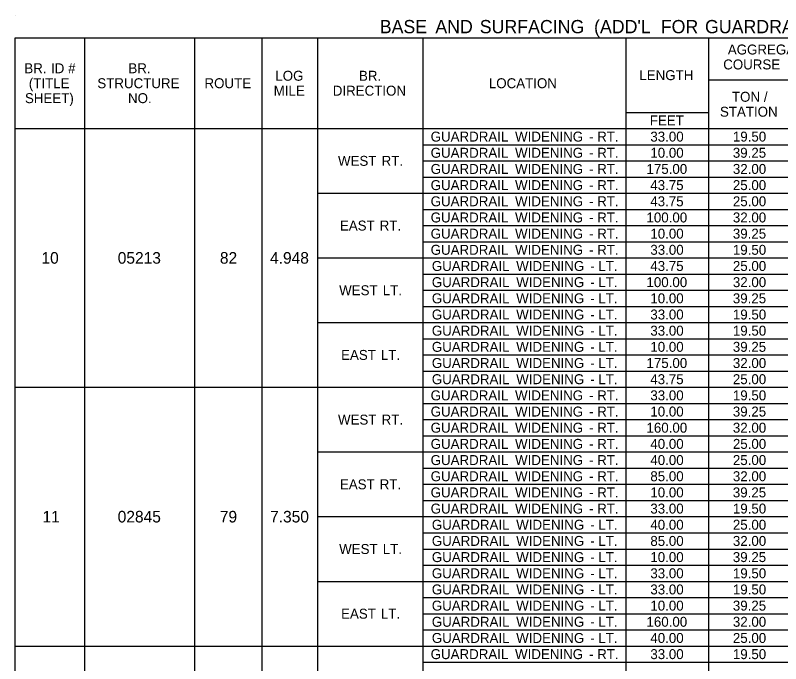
# Model space of a CAD drawing. Extents: x 544478 to 1930787, y -1948294 to 596640.
# Drawn here: x 554061.9 to 554523.1, y -1946526.7 to -1946135.8 of the extents above; entities that cross this region are included whole.
import ezdxf

# ---------------------------------------------------------------- set-up
doc = ezdxf.new("R2010")
doc.units = 0
doc.layers.add('Default', color=7, linetype='Continuous')

msp = doc.modelspace()

# ---------------------------------------------------------------- linework, layer by layer
at = {"layer": 'Default'}
for p, q in [((554061.9, -1946135.77), (554061.9, -1946135.77)), ((554061.9, -1946149.42), (554884.32, -1946149.42)), ((554061.9, -1946672.02), (554061.9, -1946149.42)), ((554103.83, -1946204.02), (554103.83, -1946149.42)), ((554170.13, -1946204.02), (554170.13, -1946149.42)), ((554210.59, -1946204.02), (554210.59, -1946149.42)), ((554244.23, -1946672.02), (554244.23, -1946149.42)), ((554307.6, -1946681.77), (554307.6, -1946149.42)), ((554429.97, -1946672.02), (554429.97, -1946149.42)), ((554479.69, -1946672.02), (554479.69, -1946149.42)), ((554479.69, -1946174.77), (554884.32, -1946174.77)), ((554429.97, -1946194.27), (554479.69, -1946194.27)), ((554479.69, -1946672.02), (554479.69, -1946194.27)), ((554061.9, -1946204.02), (554884.32, -1946204.02)), ((554103.83, -1946672.02), (554103.83, -1946204.02)), ((554170.13, -1946672.02), (554170.13, -1946204.02)), ((554210.59, -1946672.02), (554210.59, -1946204.02)), ((554429.97, -1946672.02), (554429.97, -1946204.02)), ((554479.69, -1946204.02), (554638.62, -1946204.02)), ((554307.6, -1946213.77), (554884.32, -1946213.77)), ((554307.6, -1946223.52), (554884.32, -1946223.52)), ((554307.6, -1946233.27), (554884.32, -1946233.27)), ((554244.23, -1946243.02), (554307.6, -1946243.02)), ((554307.6, -1946243.02), (554884.32, -1946243.02)), ((554307.6, -1946252.77), (554884.32, -1946252.77)), ((554307.6, -1946262.52), (554884.32, -1946262.52)), ((554307.6, -1946272.27), (554884.32, -1946272.27)), ((554244.23, -1946282.02), (554307.6, -1946282.02)), ((554307.6, -1946282.02), (554884.32, -1946282.02)), ((554307.6, -1946291.77), (554884.32, -1946291.77)), ((554307.6, -1946301.52), (554884.32, -1946301.52)), ((554307.6, -1946311.27), (554884.32, -1946311.27)), ((554244.23, -1946321.02), (554307.6, -1946321.02)), ((554307.6, -1946321.02), (554581.58, -1946321.02)), ((554307.6, -1946330.77), (554884.32, -1946330.77)), ((554307.6, -1946340.52), (554581.58, -1946340.52)), ((554307.6, -1946350.27), (554581.58, -1946350.27)), ((554061.9, -1946360.02), (554884.32, -1946360.02)), ((554307.6, -1946369.77), (554884.32, -1946369.77)), ((554307.6, -1946379.52), (554884.32, -1946379.52)), ((554307.6, -1946389.27), (554884.32, -1946389.27)), ((554244.23, -1946399.02), (554307.6, -1946399.02)), ((554307.6, -1946399.02), (554884.32, -1946399.02)), ((554307.6, -1946408.77), (554884.32, -1946408.77)), ((554307.6, -1946418.52), (554884.32, -1946418.52)), ((554307.6, -1946428.27), (554884.32, -1946428.27)), ((554244.23, -1946438.02), (554307.6, -1946438.02)), ((554307.6, -1946438.02), (554884.32, -1946438.02)), ((554307.6, -1946447.77), (554884.32, -1946447.77)), ((554307.6, -1946457.52), (554884.32, -1946457.52)), ((554307.6, -1946467.27), (554884.32, -1946467.27)), ((554244.23, -1946477.02), (554307.6, -1946477.02)), ((554307.6, -1946477.02), (554581.58, -1946477.02)), ((554307.6, -1946486.77), (554884.32, -1946486.77)), ((554307.6, -1946496.52), (554581.58, -1946496.52)), ((554307.6, -1946506.27), (554581.58, -1946506.27)), ((554061.9, -1946516.02), (554884.32, -1946516.02)), ((554307.6, -1946525.77), (554884.32, -1946525.77))]:
    msp.add_line(p, q, dxfattribs=at)

# ---------------------------------------------------------------- texts
for s, height, p in [('BASE', 8, (554281.5, -1946146.6)), (' AND', 8, (554312.01, -1946146.6)), (' SURFACING', 8, (554338.78, -1946146.6)), (" (ADD'L", 8, (554407.65, -1946146.6)), (' FOR', 8, (554447.85, -1946146.6)), (' GUARDRAIL)', 8, (554474.5, -1946146.6)), ('AGGREGATE', 6, (554491.22, -1946159.4)), ('BR.', 6, (554067.34, -1946170.72)), (' ID', 6, (554081.2, -1946170.72)), (' #', 6, (554091.5, -1946170.72)), ('BR.', 6, (554130.05, -1946170.72)), ('COURSE', 6, (554488.45, -1946168.4)), ('LOG', 6, (554218.58, -1946175.22)), ('BR.', 6, (554268.98, -1946175.22)), ('LENGTH', 6, (554437.92, -1946174.85)), ('(TITLE', 6, (554070.03, -1946179.72)), ('STRUCTURE', 6, (554111.33, -1946179.72)), ('ROUTE', 6, (554175.89, -1946179.72)), ('LOCATION', 6, (554347.23, -1946179.72)), ('MILE', 6, (554217.6, -1946184.22)), ('DIRECTION', 6, (554253.2, -1946184.22)), ('SHEET)', 6, (554067.71, -1946188.72)), ('NO.', 6, (554129.81, -1946188.72)), ('TON', 6, (554493.71, -1946187.9)), (' /', 6, (554510.73, -1946187.9)), ('STATION', 6, (554486.49, -1946196.9)), ('FEET', 6, (554444.2, -1946202.15)), ('GUARDRAIL', 6, (554312.17, -1946211.9)), (' WIDENING', 6, (554360.79, -1946211.9)), (' RT.', 6, (554410.29, -1946211.9)), ('33.00', 6, (554444.54, -1946211.9)), ('19.50', 6, (554494.27, -1946211.9)), (' -', 6, (554405.44, -1946211.9)), ('GUARDRAIL', 6, (554312.17, -1946221.65)), (' WIDENING', 6, (554360.79, -1946221.65)), (' RT.', 6, (554410.29, -1946221.65)), ('10.00', 6, (554444.54, -1946221.65)), ('39.25', 6, (554494.24, -1946221.65)), ('WEST', 6, (554256.34, -1946226.52)), (' -', 6, (554405.44, -1946221.65)), (' RT.', 6, (554280.39, -1946226.52)), ('GUARDRAIL', 6, (554312.17, -1946231.4)), (' WIDENING', 6, (554360.79, -1946231.4)), (' -', 6, (554405.44, -1946231.4)), (' RT.', 6, (554410.29, -1946231.4)), ('175.00', 6, (554442.21, -1946231.4)), ('32.00', 6, (554494.27, -1946231.4)), ('GUARDRAIL', 6, (554312.17, -1946241.15)), (' WIDENING', 6, (554360.79, -1946241.15)), (' -', 6, (554405.44, -1946241.15)), (' RT.', 6, (554410.29, -1946241.15)), ('43.75', 6, (554444.51, -1946241.15)), ('25.00', 6, (554494.27, -1946241.15)), ('GUARDRAIL', 6, (554312.17, -1946250.9)), (' WIDENING', 6, (554360.79, -1946250.9)), (' RT.', 6, (554410.29, -1946250.9)), ('43.75', 6, (554444.51, -1946250.9)), ('25.00', 6, (554494.27, -1946250.9)), (' -', 6, (554405.44, -1946250.9)), ('GUARDRAIL', 6, (554312.17, -1946260.65)), (' WIDENING', 6, (554360.79, -1946260.65)), (' RT.', 6, (554410.29, -1946260.65)), ('100.00', 6, (554442.21, -1946260.65)), ('32.00', 6, (554494.27, -1946260.65)), ('EAST', 6, (554257.5, -1946265.52)), (' RT.', 6, (554279.23, -1946265.52)), (' -', 6, (554405.44, -1946260.65)), ('GUARDRAIL', 6, (554312.17, -1946270.4)), (' WIDENING', 6, (554360.79, -1946270.4)), (' RT.', 6, (554410.29, -1946270.4)), ('10.00', 6, (554444.54, -1946270.4)), ('39.25', 6, (554494.24, -1946270.4)), (' -', 6, (554405.44, -1946270.4)), ('GUARDRAIL', 6, (554312.17, -1946280.15)), (' WIDENING', 6, (554360.79, -1946280.15)), (' RT.', 6, (554410.29, -1946280.15)), ('33.00', 6, (554444.54, -1946280.15)), ('19.50', 6, (554494.27, -1946280.15)), ('10', 7, (554077.66, -1946285.52)), ('05213', 7, (554123.61, -1946285.52)), ('82', 7, (554185.18, -1946285.52)), ('4.948', 7, (554215.39, -1946285.52)), (' -', 6, (554405.44, -1946280.15)), ('GUARDRAIL', 6, (554312.87, -1946289.9)), (' WIDENING', 6, (554361.49, -1946289.9)), (' LT.', 6, (554410.99, -1946289.9)), ('43.75', 6, (554444.51, -1946289.9)), ('25.00', 6, (554494.27, -1946289.9)), (' -', 6, (554406.14, -1946289.9)), ('GUARDRAIL', 6, (554312.87, -1946299.65)), (' WIDENING', 6, (554361.49, -1946299.65)), (' LT.', 6, (554410.99, -1946299.65)), ('100.00', 6, (554442.21, -1946299.65)), ('32.00', 6, (554494.27, -1946299.65)), ('WEST', 6, (554257.04, -1946304.52)), (' LT.', 6, (554281.09, -1946304.52)), (' -', 6, (554406.14, -1946299.65)), ('GUARDRAIL', 6, (554312.87, -1946309.4)), (' WIDENING', 6, (554361.49, -1946309.4)), (' LT.', 6, (554410.99, -1946309.4)), ('10.00', 6, (554444.54, -1946309.4)), ('39.25', 6, (554494.24, -1946309.4)), (' -', 6, (554406.14, -1946309.4)), ('GUARDRAIL', 6, (554312.87, -1946319.15)), (' WIDENING', 6, (554361.49, -1946319.15)), (' -', 6, (554406.14, -1946319.15)), (' LT.', 6, (554410.99, -1946319.15)), ('33.00', 6, (554444.54, -1946319.15)), ('19.50', 6, (554494.27, -1946319.15)), ('GUARDRAIL', 6, (554312.87, -1946328.9)), (' WIDENING', 6, (554361.49, -1946328.9)), (' -', 6, (554406.14, -1946328.9)), (' LT.', 6, (554410.99, -1946328.9)), ('33.00', 6, (554444.54, -1946328.9)), ('19.50', 6, (554494.27, -1946328.9)), ('GUARDRAIL', 6, (554312.87, -1946338.65)), (' WIDENING', 6, (554361.49, -1946338.65)), (' LT.', 6, (554410.99, -1946338.65)), ('10.00', 6, (554444.54, -1946338.65)), ('39.25', 6, (554494.24, -1946338.65)), ('EAST', 6, (554258.2, -1946343.52)), (' LT.', 6, (554279.93, -1946343.52)), (' -', 6, (554406.14, -1946338.65)), ('GUARDRAIL', 6, (554312.87, -1946348.4)), (' WIDENING', 6, (554361.49, -1946348.4)), (' LT.', 6, (554410.99, -1946348.4)), ('175.00', 6, (554442.21, -1946348.4)), ('32.00', 6, (554494.27, -1946348.4)), (' -', 6, (554406.14, -1946348.4)), ('GUARDRAIL', 6, (554312.87, -1946358.15)), (' WIDENING', 6, (554361.49, -1946358.15)), (' LT.', 6, (554410.99, -1946358.15)), ('43.75', 6, (554444.51, -1946358.15)), ('25.00', 6, (554494.27, -1946358.15)), (' -', 6, (554406.14, -1946358.15)), ('GUARDRAIL', 6, (554312.17, -1946367.9)), (' WIDENING', 6, (554360.79, -1946367.9)), (' RT.', 6, (554410.29, -1946367.9)), ('33.00', 6, (554444.54, -1946367.9)), ('19.50', 6, (554494.27, -1946367.9)), (' -', 6, (554405.44, -1946367.9)), ('GUARDRAIL', 6, (554312.17, -1946377.65)), (' WIDENING', 6, (554360.79, -1946377.65)), (' RT.', 6, (554410.29, -1946377.65)), ('10.00', 6, (554444.54, -1946377.65)), ('39.25', 6, (554494.24, -1946377.65)), ('WEST', 6, (554256.34, -1946382.52)), (' RT.', 6, (554280.39, -1946382.52)), (' -', 6, (554405.44, -1946377.65)), ('GUARDRAIL', 6, (554312.17, -1946387.4)), (' WIDENING', 6, (554360.79, -1946387.4)), (' RT.', 6, (554410.29, -1946387.4)), ('160.00', 6, (554442.21, -1946387.4)), ('32.00', 6, (554494.27, -1946387.4)), (' -', 6, (554405.44, -1946387.4)), ('GUARDRAIL', 6, (554312.17, -1946397.15)), (' WIDENING', 6, (554360.79, -1946397.15)), ('40.00', 6, (554444.54, -1946397.15)), ('25.00', 6, (554494.27, -1946397.15)), (' -', 6, (554405.44, -1946397.15)), (' RT.', 6, (554410.29, -1946397.15)), ('GUARDRAIL', 6, (554312.17, -1946406.9)), (' WIDENING', 6, (554360.79, -1946406.9)), (' -', 6, (554405.44, -1946406.9)), (' RT.', 6, (554410.29, -1946406.9)), ('40.00', 6, (554444.54, -1946406.9)), ('25.00', 6, (554494.27, -1946406.9)), ('GUARDRAIL', 6, (554312.17, -1946416.65)), (' WIDENING', 6, (554360.79, -1946416.65)), (' -', 6, (554405.44, -1946416.65)), (' RT.', 6, (554410.29, -1946416.65)), ('85.00', 6, (554444.54, -1946416.65)), ('32.00', 6, (554494.27, -1946416.65)), ('EAST', 6, (554257.5, -1946421.52)), (' RT.', 6, (554279.23, -1946421.52)), ('GUARDRAIL', 6, (554312.17, -1946426.4)), (' WIDENING', 6, (554360.79, -1946426.4)), (' RT.', 6, (554410.29, -1946426.4)), ('10.00', 6, (554444.54, -1946426.4)), ('39.25', 6, (554494.24, -1946426.4)), (' -', 6, (554405.44, -1946426.4)), ('GUARDRAIL', 6, (554312.17, -1946436.15)), (' WIDENING', 6, (554360.79, -1946436.15)), (' RT.', 6, (554410.29, -1946436.15)), ('33.00', 6, (554444.54, -1946436.15)), ('19.50', 6, (554494.27, -1946436.15)), ('11', 7, (554078.33, -1946441.52)), ('02845', 7, (554123.58, -1946441.52)), ('79', 7, (554185.14, -1946441.52)), ('7.350', 7, (554215.41, -1946441.52)), (' -', 6, (554405.44, -1946436.15)), ('GUARDRAIL', 6, (554312.87, -1946445.9)), (' WIDENING', 6, (554361.49, -1946445.9)), (' LT.', 6, (554410.99, -1946445.9)), ('40.00', 6, (554444.54, -1946445.9)), ('25.00', 6, (554494.27, -1946445.9)), (' -', 6, (554406.14, -1946445.9)), ('GUARDRAIL', 6, (554312.87, -1946455.65)), (' WIDENING', 6, (554361.49, -1946455.65)), (' LT.', 6, (554410.99, -1946455.65)), ('85.00', 6, (554444.54, -1946455.65)), ('32.00', 6, (554494.27, -1946455.65)), ('WEST', 6, (554257.04, -1946460.52)), (' LT.', 6, (554281.09, -1946460.52)), (' -', 6, (554406.14, -1946455.65)), ('GUARDRAIL', 6, (554312.87, -1946465.4)), (' WIDENING', 6, (554361.49, -1946465.4)), (' LT.', 6, (554410.99, -1946465.4)), ('10.00', 6, (554444.54, -1946465.4)), ('39.25', 6, (554494.24, -1946465.4)), (' -', 6, (554406.14, -1946465.4)), ('GUARDRAIL', 6, (554312.87, -1946475.15)), (' WIDENING', 6, (554361.49, -1946475.15)), (' LT.', 6, (554410.99, -1946475.15)), ('33.00', 6, (554444.54, -1946475.15)), ('19.50', 6, (554494.27, -1946475.15)), (' -', 6, (554406.14, -1946475.15)), ('GUARDRAIL', 6, (554312.87, -1946484.9)), (' WIDENING', 6, (554361.49, -1946484.9)), (' -', 6, (554406.14, -1946484.9)), (' LT.', 6, (554410.99, -1946484.9)), ('33.00', 6, (554444.54, -1946484.9)), ('19.50', 6, (554494.27, -1946484.9)), ('GUARDRAIL', 6, (554312.87, -1946494.65)), (' WIDENING', 6, (554361.49, -1946494.65)), (' -', 6, (554406.14, -1946494.65)), (' LT.', 6, (554410.99, -1946494.65)), ('10.00', 6, (554444.54, -1946494.65)), ('39.25', 6, (554494.24, -1946494.65)), ('EAST', 6, (554258.2, -1946499.52)), (' LT.', 6, (554279.93, -1946499.52)), ('GUARDRAIL', 6, (554312.87, -1946504.4)), (' WIDENING', 6, (554361.49, -1946504.4)), (' -', 6, (554406.14, -1946504.4)), (' LT.', 6, (554410.99, -1946504.4)), ('160.00', 6, (554442.21, -1946504.4)), ('32.00', 6, (554494.27, -1946504.4)), ('GUARDRAIL', 6, (554312.87, -1946514.15)), (' WIDENING', 6, (554361.49, -1946514.15)), (' LT.', 6, (554410.99, -1946514.15)), ('40.00', 6, (554444.54, -1946514.15)), ('25.00', 6, (554494.27, -1946514.15)), (' -', 6, (554406.14, -1946514.15)), ('GUARDRAIL', 6, (554312.17, -1946523.9)), (' WIDENING', 6, (554360.79, -1946523.9)), (' RT.', 6, (554410.29, -1946523.9)), ('33.00', 6, (554444.54, -1946523.9)), ('19.50', 6, (554494.27, -1946523.9)), (' -', 6, (554405.44, -1946523.9))]:
    msp.add_text(s, height=height, dxfattribs=at).set_placement(p)

doc.saveas('drawing.dxf')
